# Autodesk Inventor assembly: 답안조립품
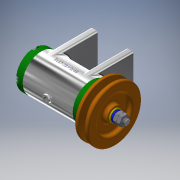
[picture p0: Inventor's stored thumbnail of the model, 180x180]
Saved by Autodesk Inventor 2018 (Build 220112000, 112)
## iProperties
Created: 2020-07
Part Number: 답안조립품
Material: 일반
Document SubType Name: Assembly
Designer: home
Author: home
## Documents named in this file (15)
- C:\Users\home\Desktop\700706V1032\답안조립품.iam
- C:\Users\home\Desktop\700706V1032\본체.ipt
- C:\Users\home\Desktop\700706V1032\축.ipt
- C:\Users\home\Desktop\700706V1032\베어링 6002.ipt
- C:\Users\home\Desktop\700706V1032\앞커버.ipt
- C:\Users\home\Desktop\700706V1032\뒤커버.ipt
- C:\Users\home\Desktop\700706V1032\오일 실 15 25 7.ipt
- C:\Users\home\Desktop\700706V1032\볼트 M4x12.ipt
- C:\Users\home\Desktop\700706V1032\Ű 3x3x12.ipt
- C:\Users\home\Desktop\700706V1032\V벨트풀리.ipt
- C:\Users\home\Desktop\700706V1032\와셔 8x17.ipt
- C:\Users\home\Desktop\700706V1032\스프링와셔 8.ipt
- C:\Users\home\Desktop\700706V1032\너트 M8.ipt
- C:\Users\home\Desktop\700706V1032\볼트 M6x8.ipt
- C:\Users\home\Desktop\700706V1032\와셔 6x11.5.ipt
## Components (2 placed, 2 different names)
1. Ű 3x3x12:1
2. V벨트풀리:1
